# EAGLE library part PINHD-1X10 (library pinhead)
PIN HEADER
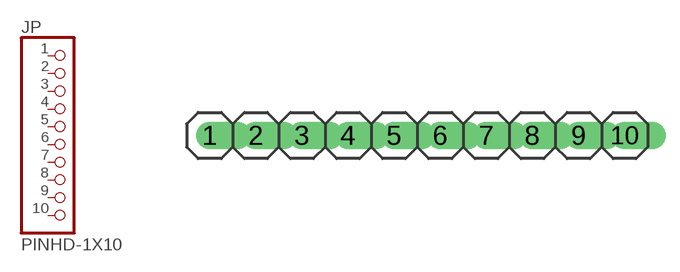
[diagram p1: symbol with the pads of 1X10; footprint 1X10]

Designator prefix JP

## PINHD-1X10  [1X10]
1  1  pas
2  2  pas
3  3  pas
4  4  pas
5  5  pas
6  6  pas
7  7  pas
8  8  pas
9  9  pas
10  10  pas

## Footprint 1X10 (pad centres in mm)
PIN HEADER
drill 1.016 offset: 1 -11.43,0; 2 -8.89,0; 3 -6.35,0; 4 -3.81,0; 5 -1.27,0; 6 1.27,0; 7 3.81,0; 8 6.35,0; 9 8.89,0; 10 11.43,0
